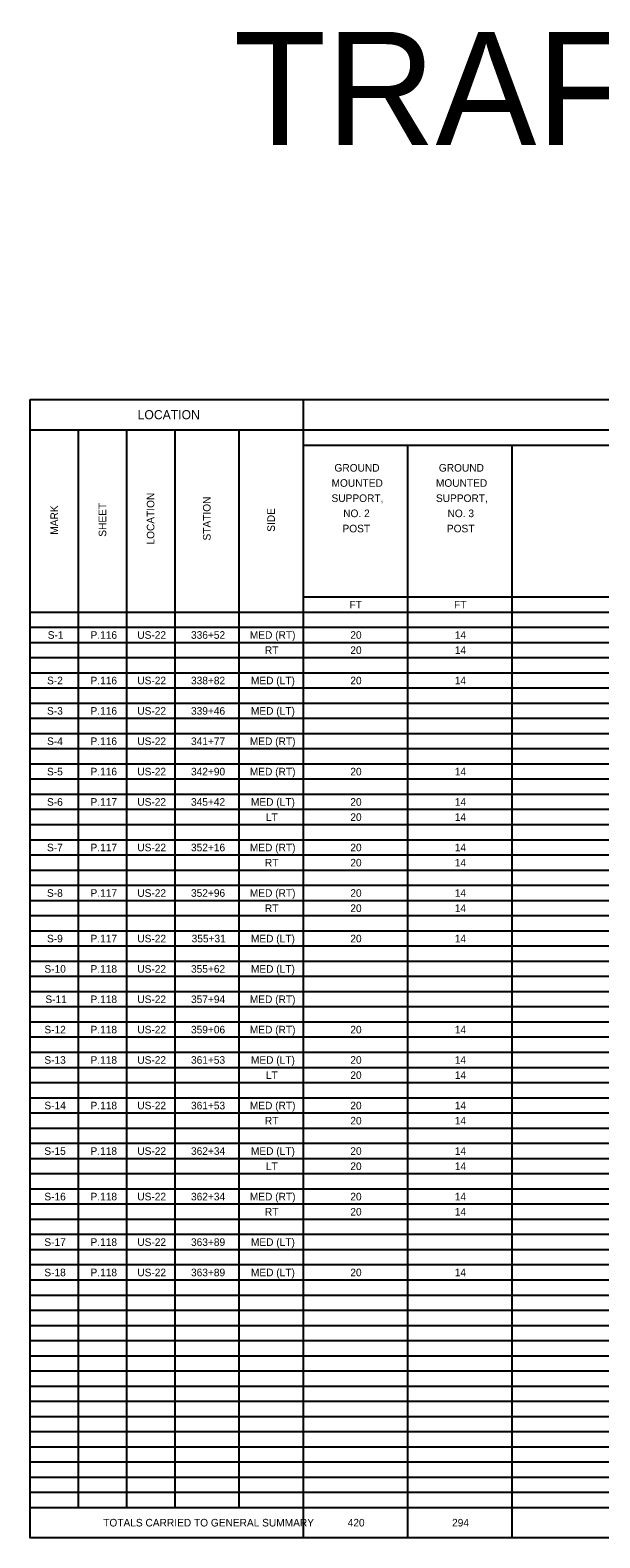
# Model space of a CAD drawing. Extents: x 12522 to 13018, y 1124 to 1902.
# Drawn here: x 12911.11 to 12921.63, y 1828.79 to 1856.61 of the extents above; entities that cross this region are included whole.
import ezdxf

# ---------------------------------------------------------------- set-up
doc = ezdxf.new("R2010")
doc.units = 0
for name, color, linetype in [('SC_Scratch1', 7, 'Continuous'), ('SH_Data', 7, 'Continuous'), ('SH_Text', 7, 'Continuous')]:
    doc.layers.add(name, color=color, linetype=linetype)

msp = doc.modelspace()

# ---------------------------------------------------------------- linework, layer by layer
at = {"layer": 'SC_Scratch1'}
msp.add_lwpolyline([(12911.11, 1849.791), (12941.61, 1849.791), (12941.61, 1828.791), (12911.11, 1828.791)], close=True, dxfattribs=at)
at = {"layer": 'SH_Data'}
for p, q in [((12916.15, 1849.791), (12916.15, 1828.791)), ((12911.11, 1849.231), (12941.597, 1849.231)), ((12911.999, 1849.231), (12911.999, 1829.351)), ((12912.888, 1849.231), (12912.888, 1829.351)), ((12913.778, 1849.231), (12913.778, 1829.351)), ((12914.964, 1849.231), (12914.964, 1829.351)), ((12916.15, 1848.951), (12941.597, 1848.951)), ((12918.077, 1848.951), (12918.077, 1828.791)), ((12920.004, 1848.951), (12920.004, 1828.791)), ((12916.15, 1846.151), (12941.597, 1846.151)), ((12911.11, 1845.871), (12941.597, 1845.871)), ((12911.11, 1845.591), (12941.597, 1845.591)), ((12911.11, 1845.311), (12941.597, 1845.311)), ((12911.11, 1845.031), (12941.597, 1845.031)), ((12911.11, 1844.751), (12941.597, 1844.751)), ((12911.11, 1844.471), (12941.597, 1844.471)), ((12911.11, 1844.191), (12941.597, 1844.191)), ((12911.11, 1843.911), (12941.597, 1843.911)), ((12911.11, 1843.631), (12941.597, 1843.631)), ((12911.11, 1843.351), (12941.597, 1843.351)), ((12911.11, 1843.071), (12941.597, 1843.071)), ((12911.11, 1842.791), (12941.597, 1842.791)), ((12911.11, 1842.511), (12941.597, 1842.511)), ((12911.11, 1842.231), (12941.597, 1842.231)), ((12911.11, 1841.951), (12941.597, 1841.951)), ((12911.11, 1841.671), (12941.597, 1841.671)), ((12911.11, 1841.391), (12941.597, 1841.391)), ((12911.11, 1841.111), (12941.597, 1841.111)), ((12911.11, 1840.831), (12941.597, 1840.831)), ((12911.11, 1840.551), (12941.597, 1840.551)), ((12911.11, 1840.271), (12941.597, 1840.271)), ((12911.11, 1839.991), (12941.597, 1839.991)), ((12911.11, 1839.711), (12941.597, 1839.711)), ((12911.11, 1839.431), (12941.597, 1839.431)), ((12911.11, 1839.151), (12941.597, 1839.151)), ((12911.11, 1838.871), (12941.597, 1838.871)), ((12911.11, 1838.591), (12941.597, 1838.591)), ((12911.11, 1838.311), (12941.597, 1838.311)), ((12911.11, 1838.031), (12941.597, 1838.031)), ((12911.11, 1837.751), (12941.597, 1837.751)), ((12911.11, 1837.471), (12941.597, 1837.471)), ((12911.11, 1837.191), (12941.597, 1837.191)), ((12911.11, 1836.911), (12941.597, 1836.911)), ((12911.11, 1836.631), (12941.597, 1836.631)), ((12911.11, 1836.351), (12941.597, 1836.351)), ((12911.11, 1836.071), (12941.597, 1836.071)), ((12911.11, 1835.791), (12941.597, 1835.791)), ((12911.11, 1835.511), (12941.597, 1835.511)), ((12911.11, 1835.231), (12941.597, 1835.231)), ((12911.11, 1834.951), (12941.597, 1834.951)), ((12911.11, 1834.671), (12941.597, 1834.671)), ((12911.11, 1834.391), (12941.597, 1834.391)), ((12911.11, 1834.111), (12941.597, 1834.111)), ((12911.11, 1833.831), (12941.597, 1833.831)), ((12911.11, 1833.551), (12941.597, 1833.551)), ((12911.11, 1833.271), (12941.597, 1833.271)), ((12911.11, 1832.991), (12941.597, 1832.991)), ((12911.11, 1832.711), (12941.597, 1832.711)), ((12911.11, 1832.431), (12941.597, 1832.431)), ((12911.11, 1832.151), (12941.597, 1832.151)), ((12911.11, 1831.871), (12941.597, 1831.871)), ((12911.11, 1831.591), (12941.597, 1831.591)), ((12911.11, 1831.311), (12941.597, 1831.311)), ((12911.11, 1831.031), (12941.597, 1831.031)), ((12911.11, 1830.751), (12941.597, 1830.751)), ((12911.11, 1830.471), (12941.597, 1830.471)), ((12911.11, 1830.191), (12941.597, 1830.191)), ((12911.11, 1829.911), (12941.597, 1829.911)), ((12911.11, 1829.631), (12941.597, 1829.631)), ((12911.11, 1829.351), (12941.597, 1829.351))]:
    msp.add_line(p, q, dxfattribs=at)

# ---------------------------------------------------------------- texts
at = {"layer": 'SC_Scratch1'}
msp.add_text('TRAFFIC CONTROL', height=2.08957, dxfattribs=at).set_placement((12914.867, 1854.484))
at = {"layer": 'SH_Text'}
for s, height, p in [('LOCATION', 0.168, (12913.094, 1849.427)), ('GROUND', 0.14, (12916.727, 1848.461)), ('GROUND', 0.14, (12918.654, 1848.461)), ('MOUNTED', 0.14, (12916.673, 1848.181)), ('MOUNTED', 0.14, (12918.6, 1848.181)), ('SUPPORT,', 0.14, (12916.673, 1847.901)), ('SUPPORT,', 0.14, (12918.6, 1847.901)), ('NO. 2', 0.14, (12916.888, 1847.621)), ('NO. 3', 0.14, (12918.814, 1847.621)), ('POST', 0.14, (12916.875, 1847.341)), ('POST', 0.14, (12918.802, 1847.341)), ('FT', 0.14, (12917.007, 1845.937)), ('FT', 0.14, (12918.934, 1845.937)), ('S-1', 0.14, (12911.434, 1845.377)), ('P.116', 0.14, (12912.224, 1845.377)), ('US-22', 0.14, (12913.088, 1845.377)), ('336+52', 0.14, (12914.079, 1845.377)), ('MED (RT)', 0.14, (12915.165, 1845.377)), ('20', 0.14, (12917.02, 1845.377)), ('14', 0.14, (12918.947, 1845.377)), ('RT', 0.14, (12915.443, 1845.097)), ('20', 0.14, (12917.02, 1845.097)), ('14', 0.14, (12918.947, 1845.097)), ('S-2', 0.14, (12911.422, 1844.537)), ('P.116', 0.14, (12912.224, 1844.537)), ('US-22', 0.14, (12913.088, 1844.537)), ('338+82', 0.14, (12914.079, 1844.537)), ('MED (LT)', 0.14, (12915.185, 1844.537)), ('20', 0.14, (12917.02, 1844.537)), ('14', 0.14, (12918.947, 1844.537)), ('S-3', 0.14, (12911.421, 1843.977)), ('P.116', 0.14, (12912.224, 1843.977)), ('US-22', 0.14, (12913.088, 1843.977)), ('339+46', 0.14, (12914.079, 1843.977)), ('MED (LT)', 0.14, (12915.185, 1843.977)), ('S-4', 0.14, (12911.422, 1843.417)), ('P.116', 0.14, (12912.224, 1843.417)), ('US-22', 0.14, (12913.088, 1843.417)), ('341+77', 0.14, (12914.079, 1843.417)), ('MED (RT)', 0.14, (12915.165, 1843.417)), ('S-5', 0.14, (12911.421, 1842.857)), ('P.116', 0.14, (12912.224, 1842.857)), ('US-22', 0.14, (12913.088, 1842.857)), ('342+90', 0.14, (12914.079, 1842.857)), ('MED (RT)', 0.14, (12915.165, 1842.857)), ('20', 0.14, (12917.02, 1842.857)), ('14', 0.14, (12918.947, 1842.857)), ('S-6', 0.14, (12911.421, 1842.297)), ('P.117', 0.14, (12912.224, 1842.297)), ('US-22', 0.14, (12913.088, 1842.297)), ('345+42', 0.14, (12914.079, 1842.297)), ('MED (LT)', 0.14, (12915.185, 1842.297)), ('20', 0.14, (12917.02, 1842.297)), ('14', 0.14, (12918.947, 1842.297)), ('LT', 0.14, (12915.462, 1842.017)), ('20', 0.14, (12917.02, 1842.017)), ('14', 0.14, (12918.947, 1842.017)), ('S-7', 0.14, (12911.421, 1841.457)), ('P.117', 0.14, (12912.224, 1841.457)), ('US-22', 0.14, (12913.088, 1841.457)), ('352+16', 0.14, (12914.079, 1841.457)), ('MED (RT)', 0.14, (12915.165, 1841.457)), ('20', 0.14, (12917.02, 1841.457)), ('14', 0.14, (12918.947, 1841.457)), ('RT', 0.14, (12915.443, 1841.177)), ('20', 0.14, (12917.02, 1841.177)), ('14', 0.14, (12918.947, 1841.177)), ('S-8', 0.14, (12911.421, 1840.617)), ('P.117', 0.14, (12912.224, 1840.617)), ('US-22', 0.14, (12913.088, 1840.617)), ('352+96', 0.14, (12914.079, 1840.617)), ('MED (RT)', 0.14, (12915.165, 1840.617)), ('20', 0.14, (12917.02, 1840.617)), ('14', 0.14, (12918.947, 1840.617)), ('RT', 0.14, (12915.443, 1840.337)), ('20', 0.14, (12917.02, 1840.337)), ('14', 0.14, (12918.947, 1840.337)), ('S-9', 0.14, (12911.421, 1839.777)), ('P.117', 0.14, (12912.224, 1839.777)), ('US-22', 0.14, (12913.088, 1839.777)), ('355+31', 0.14, (12914.091, 1839.777)), ('MED (LT)', 0.14, (12915.185, 1839.777)), ('20', 0.14, (12917.02, 1839.777)), ('14', 0.14, (12918.947, 1839.777)), ('S-10', 0.14, (12911.373, 1839.217)), ('P.118', 0.14, (12912.224, 1839.217)), ('US-22', 0.14, (12913.088, 1839.217)), ('355+62', 0.14, (12914.079, 1839.217)), ('MED (LT)', 0.14, (12915.185, 1839.217)), ('S-11', 0.14, (12911.391, 1838.657)), ('P.118', 0.14, (12912.224, 1838.657)), ('US-22', 0.14, (12913.088, 1838.657)), ('357+94', 0.14, (12914.079, 1838.657)), ('MED (RT)', 0.14, (12915.165, 1838.657)), ('S-12', 0.14, (12911.373, 1838.097)), ('P.118', 0.14, (12912.224, 1838.097)), ('US-22', 0.14, (12913.088, 1838.097)), ('359+06', 0.14, (12914.079, 1838.097)), ('MED (RT)', 0.14, (12915.165, 1838.097)), ('20', 0.14, (12917.02, 1838.097)), ('14', 0.14, (12918.947, 1838.097)), ('S-13', 0.14, (12911.372, 1837.537)), ('P.118', 0.14, (12912.224, 1837.537)), ('US-22', 0.14, (12913.088, 1837.537)), ('361+53', 0.14, (12914.079, 1837.537)), ('MED (LT)', 0.14, (12915.185, 1837.537)), ('20', 0.14, (12917.02, 1837.537)), ('14', 0.14, (12918.947, 1837.537)), ('LT', 0.14, (12915.462, 1837.257)), ('20', 0.14, (12917.02, 1837.257)), ('14', 0.14, (12918.947, 1837.257)), ('S-14', 0.14, (12911.373, 1836.697)), ('P.118', 0.14, (12912.224, 1836.697)), ('US-22', 0.14, (12913.088, 1836.697)), ('361+53', 0.14, (12914.079, 1836.697)), ('MED (RT)', 0.14, (12915.165, 1836.697)), ('20', 0.14, (12917.02, 1836.697)), ('14', 0.14, (12918.947, 1836.697)), ('RT', 0.14, (12915.443, 1836.417)), ('20', 0.14, (12917.02, 1836.417)), ('14', 0.14, (12918.947, 1836.417)), ('S-15', 0.14, (12911.372, 1835.857)), ('P.118', 0.14, (12912.224, 1835.857)), ('US-22', 0.14, (12913.088, 1835.857)), ('362+34', 0.14, (12914.079, 1835.857)), ('MED (LT)', 0.14, (12915.185, 1835.857)), ('20', 0.14, (12917.02, 1835.857)), ('14', 0.14, (12918.947, 1835.857)), ('LT', 0.14, (12915.462, 1835.577)), ('20', 0.14, (12917.02, 1835.577)), ('14', 0.14, (12918.947, 1835.577)), ('S-16', 0.14, (12911.372, 1835.017)), ('P.118', 0.14, (12912.224, 1835.017)), ('US-22', 0.14, (12913.088, 1835.017)), ('362+34', 0.14, (12914.079, 1835.017)), ('MED (RT)', 0.14, (12915.165, 1835.017)), ('20', 0.14, (12917.02, 1835.017)), ('14', 0.14, (12918.947, 1835.017)), ('RT', 0.14, (12915.443, 1834.737)), ('20', 0.14, (12917.02, 1834.737)), ('14', 0.14, (12918.947, 1834.737)), ('S-17', 0.14, (12911.372, 1834.177)), ('P.118', 0.14, (12912.224, 1834.177)), ('US-22', 0.14, (12913.088, 1834.177)), ('363+89', 0.14, (12914.079, 1834.177)), ('MED (LT)', 0.14, (12915.185, 1834.177)), ('S-18', 0.14, (12911.372, 1833.617)), ('P.118', 0.14, (12912.224, 1833.617)), ('US-22', 0.14, (12913.088, 1833.617)), ('363+89', 0.14, (12914.079, 1833.617)), ('MED (LT)', 0.14, (12915.185, 1833.617)), ('20', 0.14, (12917.02, 1833.617)), ('14', 0.14, (12918.947, 1833.617)), ('TOTALS CARRIED TO GENERAL SUMMARY', 0.14, (12912.459, 1829.001)), ('420', 0.14, (12916.971, 1829.001)), ('294', 0.14, (12918.898, 1829.001))]:
    msp.add_text(s, height=height, dxfattribs=at).set_placement(p)
for s, p in [('LOCATION', (12913.403, 1847.115)), ('STATION', (12914.441, 1847.19)), ('MARK', (12911.624, 1847.297)), ('SHEET', (12912.514, 1847.26)), ('SIDE', (12915.627, 1847.351))]:
    msp.add_text(s, height=0.14, rotation=90, dxfattribs=at).set_placement(p)

doc.saveas('drawing.dxf')
